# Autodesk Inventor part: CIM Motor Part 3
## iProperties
Created: 2010-01
Part Number: CIM Motor Part 3
Document SubType Name: Modeling
Designer: cmcfadden
Density: 1 g/cm^3
Author: cmcfadden
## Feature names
1. Extrusion1
2. Fillet1
3. Extrusion2
4. Chamfer1
5. Extrusion3
6. Extrusion4
